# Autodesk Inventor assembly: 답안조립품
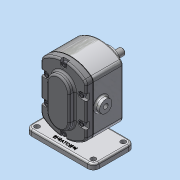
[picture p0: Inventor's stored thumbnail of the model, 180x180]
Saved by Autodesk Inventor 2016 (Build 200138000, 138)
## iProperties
Created: 2019-03
Part Number: 답안조립품
Material: 일반
Document SubType Name: Assembly
Designer: Administrator
Author: Administrator
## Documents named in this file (11)
- C:\Users\Administrator\Desktop\490307V1029\답안조립품.iam
- C:\Users\Administrator\Desktop\490307V1029\본체.ipt
- C:\Users\Administrator\Desktop\490307V1029\메인축.ipt
- C:\Users\Administrator\Desktop\490307V1029\베어링부시.ipt
- C:\Users\Administrator\Desktop\490307V1029\키 6 x 6 x 18.ipt
- C:\Users\Administrator\Desktop\490307V1029\스퍼기어.ipt
- C:\Users\Administrator\Desktop\490307V1029\서브축.ipt
- C:\Users\Administrator\Desktop\490307V1029\오일 실 16 28 7.ipt
- C:\Users\Administrator\Desktop\490307V1029\커버.ipt
- C:\Users\Administrator\Desktop\490307V1029\개스킷.ipt
- C:\Users\Administrator\Desktop\490307V1029\볼트 M5.ipt
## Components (1 placed, 1 different names)
1. 개스킷:1
